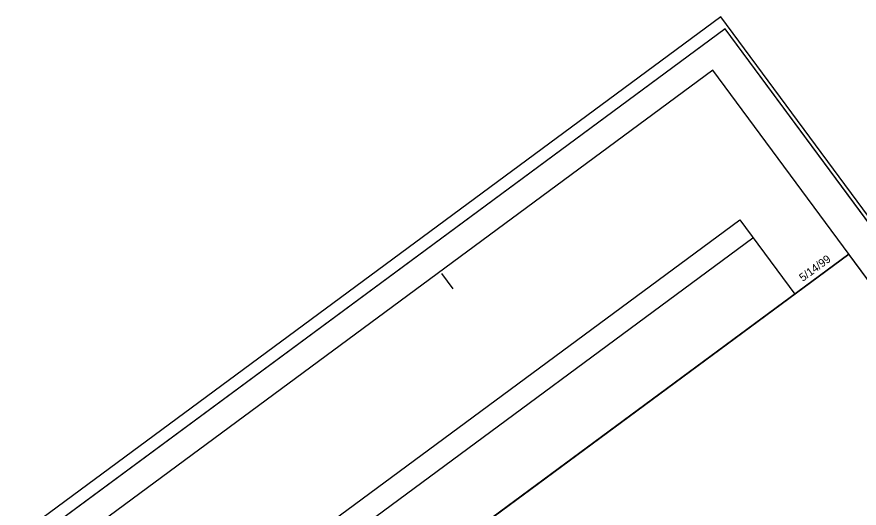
# Model space of a CAD drawing. Extents: x 1762445 to 1764340, y 710860 to 712881.
# Drawn here: x 1762868 to 1763421, y 712559 to 712881 of the extents above; entities that cross this region are included whole.
import ezdxf

# ---------------------------------------------------------------- set-up
doc = ezdxf.new("R2010")
doc.units = 0
for name, color, linetype in [('Old_Level_5', 7, 'Continuous'), ('Old_Level_62', 7, 'Continuous'), ('Old_Level_63', 7, 'Continuous'), ('Prop Conc Curb 8in x 12in', 7, 'Continuous'), ('Prop Conc Island Cover', 7, 'Continuous'), ('Prop Dimension', 7, 'Continuous'), ('Prop North Arrow NAD83 for Plan Sheets CELL', 7, 'Continuous'), ('Prop Terminator CELL', 7, 'Continuous'), ('Scratch_Level_3', 7, 'Continuous')]:
    doc.layers.add(name, color=color, linetype=linetype)

msp = doc.modelspace()

# ---------------------------------------------------------------- linework, layer by layer
at = {"layer": 'Old_Level_5'}
msp.add_lwpolyline([(1764333.55, 711519.06), (1763332.68, 712873.36), (1762448.05, 712219.58), (1763448.92, 710865.29)], close=True, dxfattribs=at)
at = {"layer": 'Old_Level_62'}
msp.add_lwpolyline([(1762480.31, 712222.29), (1763460.97, 710895.33), (1764305.39, 711519.39), (1763324.73, 712846.34)], close=True, dxfattribs=at)
at = {"layer": 'Old_Level_63'}
msp.add_lwpolyline([(1762445.34, 712227.53), (1763455.72, 710860.37), (1764340.36, 711514.14), (1763329.98, 712881.31)], close=True, dxfattribs=at)
at = {"layer": 'Prop Conc Curb 8in x 12in'}
msp.add_line((1763413.88, 712725.71), (1763413.88, 712725.71), dxfattribs=at)
at = {"layer": 'Prop Conc Island Cover'}
msp.add_line((1763146.68, 712712.9), (1763154.11, 712702.84), dxfattribs=at)
at = {"layer": 'Prop Dimension'}
msp.add_lwpolyline([(1764305.39, 711519.39), (1763413.88, 712725.71), (1762569.46, 712101.65), (1763460.97, 710895.33)], close=True, dxfattribs=at)
at = {"layer": 'Prop North Arrow NAD83 for Plan Sheets CELL'}
msp.add_line((1762991.67, 712413.68), (1763413.88, 712725.71), dxfattribs=at)
at = {"layer": 'Prop Terminator CELL'}
for p, q in [((1763332.68, 712873.36), (1762448.05, 712219.58)), ((1764333.55, 711519.06), (1763332.68, 712873.36))]:
    msp.add_line(p, q, dxfattribs=at)
at = {"layer": 'Scratch_Level_3'}
msp.add_line((1762715.11, 712266.48), (1763350.95, 712736.4), dxfattribs=at)
msp.add_lwpolyline([(1762706.45, 712278.17), (1763342.3, 712748.08), (1763378.3, 712699.41), (1762742.45, 712229.5)], close=True, dxfattribs=at)

# ---------------------------------------------------------------- texts
at = {"layer": 'Prop Dimension'}
msp.add_text('5/14/99', height=5.25, rotation=36.4657, dxfattribs=at).set_placement((1763383.64, 712707.4))

doc.saveas('drawing.dxf')
